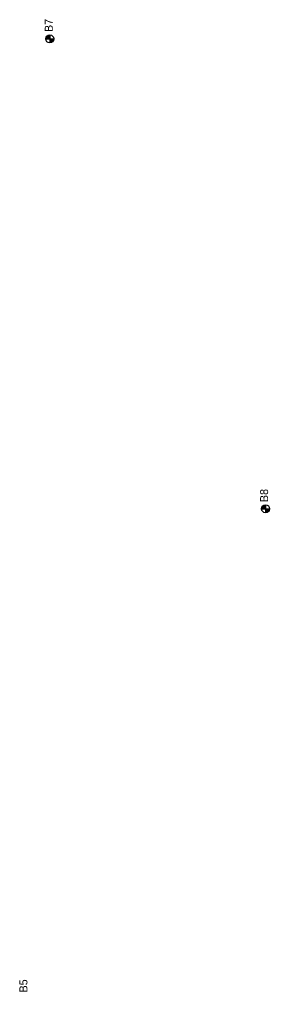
# Model space of a CAD drawing. Extents: x 345549 to 379569, y 127949 to 230467.
# Drawn here: x 361394 to 361707, y 130810 to 132024 of the extents above; entities that cross this region are included whole.
import ezdxf

# ---------------------------------------------------------------- set-up
doc = ezdxf.new("R2010")
doc.units = 0
for name, color, linetype in [('E_SOIL_BORE1 [KAPUR_CADDS_LEVELS]', 7, 'Continuous'), ('E_SOIL_BORE2 [KAPUR_CADDS_LEVELS]', 7, 'Continuous'), ('P_MARK', 7, 'Continuous')]:
    doc.layers.add(name, color=color, linetype=linetype)

msp = doc.modelspace()

# ---------------------------------------------------------------- linework, layer by layer
at = {"layer": 'P_MARK'}
for p, q in [((361427.2, 132000.1), (361437.2, 132000.1)), ((361432.2, 132005.1), (361432.2, 131995.1)), ((361697, 131413), (361707, 131413)), ((361702, 131418), (361702, 131408))]:
    msp.add_line(p, q, dxfattribs=at)
for centre in [(361432.2, 132000.1), (361702, 131413)]:
    msp.add_circle(centre, 5, dxfattribs=at)
for centre, radius, start, end in [((361432.2, 132000.1), 4.5, 89.9869, 179.9869), ((361432.2, 132000.1), 4, 89.9869, 179.9869), ((361432.2, 132000.1), 3.5, 89.9869, 179.9869), ((361432.2, 132000.1), 3, 89.9869, 179.9869), ((361432.2, 132000.1), 2.5, 89.9869, 179.9869), ((361432.2, 132000.1), 2, 89.9869, 179.9869), ((361432.2, 132000.1), 1.5, 89.9869, 179.9869), ((361432.2, 132000.1), 1, 89.9869, 179.9869), ((361432.2, 132000.1), 0.5, 89.9869, 179.9869), ((361432.2, 132000.1), 4.5, 269.9869, 359.9869), ((361432.2, 132000.1), 4, 269.9869, 359.9869), ((361432.2, 132000.1), 3.5, 269.9869, 359.9869), ((361432.2, 132000.1), 3, 269.9869, 359.9869), ((361432.2, 132000.1), 2.5, 269.9869, 359.9869), ((361432.2, 132000.1), 2, 269.9869, 359.9869), ((361432.2, 132000.1), 1.5, 269.9869, 359.9869), ((361432.2, 132000.1), 1, 269.9869, 359.9869), ((361432.2, 132000.1), 0.5, 269.9869, 359.9869), ((361702, 131413), 4.5, 89.9869, 179.9869), ((361702, 131413), 4, 89.9869, 179.9869), ((361702, 131413), 3.5, 89.9869, 179.9869), ((361702, 131413), 3, 89.9869, 179.9869), ((361702, 131413), 2.5, 89.9869, 179.9869), ((361702, 131413), 2, 89.9869, 179.9869), ((361702, 131413), 1.5, 89.9869, 179.9869), ((361702, 131413), 1, 89.9869, 179.9869), ((361702, 131413), 0.5, 89.9869, 179.9869), ((361702, 131413), 4.5, 269.9869, 359.9869), ((361702, 131413), 4, 269.9869, 359.9869), ((361702, 131413), 3.5, 269.9869, 359.9869), ((361702, 131413), 3, 269.9869, 359.9869), ((361702, 131413), 2.5, 269.9869, 359.9869), ((361702, 131413), 2, 269.9869, 359.9869), ((361702, 131413), 1.5, 269.9869, 359.9869), ((361702, 131413), 1, 269.9869, 359.9869), ((361702, 131413), 0.5, 269.9869, 359.9869)]:
    msp.add_arc(centre, radius, start, end, dxfattribs=at)

# ---------------------------------------------------------------- texts
at = {"layer": 'E_SOIL_BORE1 [KAPUR_CADDS_LEVELS]'}
for s, p in [('B7', (361435.9, 132008.7)), ('B8', (361705.2, 131421.4))]:
    msp.add_text(s, height=10, rotation=89.9869, dxfattribs=at).set_placement(p)
at = {"layer": 'E_SOIL_BORE2 [KAPUR_CADDS_LEVELS]'}
msp.add_text('B5', height=10, rotation=89.9869, dxfattribs=at).set_placement((361404.2, 130808.8))

doc.saveas('drawing.dxf')
